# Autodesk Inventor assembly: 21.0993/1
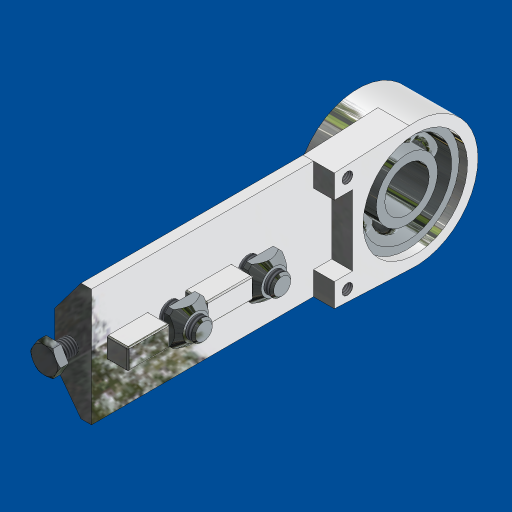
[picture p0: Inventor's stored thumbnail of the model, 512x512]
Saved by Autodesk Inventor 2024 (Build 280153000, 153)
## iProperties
Created: 2007-04
Part Number: 21.0993/1
Document SubType Name: Assembly
Designer: Andy Moles
Description: CONVEYOR BEARING 45 WITH BORE
Stock Number: 21.0993/1 CONVEYOR BEARING 45 WITH BORE
Author: Andy Moles
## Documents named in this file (6)
- L:\INVENTOR LIBRARIES\PARTS LIBRARY\BELT AND ROLLER CONVEYORS\21.0993_1 CONVEYOR BEARING 45 WITH BORE.iam
- L:\INVENTOR LIBRARIES\PARTS LIBRARY\BELT AND ROLLER CONVEYORS\SUBCOMPONENTS\21.0993_1 CONVEYOR BEARING 45 WITH BORE.ipt
- L:\INVENTOR LIBRARIES\PARTS LIBRARY\BELT AND ROLLER CONVEYORS\SUBCOMPONENTS\21.0993 CONVEYOR BEARING 45 M6X25.ipt
- L:\INVENTOR LIBRARIES\PARTS LIBRARY\FASTENING ELEMENTS\SCREWS CAP\21.1200 M8X16.ipt
- L:\INVENTOR LIBRARIES\PARTS LIBRARY\FASTENING ELEMENTS\NUTS\21.1351 M8 SQUARE NUT.ipt
- L:\INVENTOR LIBRARIES\PARTS LIBRARY\BELT AND ROLLER CONVEYORS\SUBCOMPONENTS\21.0993 15mm GRAY END CAP SHORT.ipt
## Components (8 placed, 5 different names)
1. 21.0993_1 CONVEYOR BEARING 45 WITH BORE:1 — Flush:1, Mate:1, Flush:2, Insert:1, Insert:2, Insert:3, Insert:4, Insert:5, Insert:6, Insert:7
2. 21.0993 CONVEYOR BEARING 45 M6X25:1 — Insert:1
3. 21.1200 M8 x 16:1 — Insert:2
4. 21.1200 M8 x 16:2 — Insert:3
5. 21.1351 M8 SQUARE NUT:1 — Insert:4
6. 21.1351 M8 SQUARE NUT:2 — Insert:5
7. 21.0993 15mm GRAY END CAP SHORT:1 — Insert:6
8. 21.0993 15mm GRAY END CAP SHORT:2 — Insert:7
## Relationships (10: Insert 7, Flush 2, Mate 1)
- Flush:1: 21.0993_1 CONVEYOR BEARING 45 WITH BORE:1
- Mate:1: 21.0993_1 CONVEYOR BEARING 45 WITH BORE:1
- Flush:2: 21.0993_1 CONVEYOR BEARING 45 WITH BORE:1
- Insert:1: 21.0993_1 CONVEYOR BEARING 45 WITH BORE:1 ↔ 21.0993 CONVEYOR BEARING 45 M6X25:1
- Insert:2: 21.0993_1 CONVEYOR BEARING 45 WITH BORE:1 ↔ 21.1200 M8 x 16:1
- Insert:3: 21.0993_1 CONVEYOR BEARING 45 WITH BORE:1 ↔ 21.1200 M8 x 16:2
- Insert:4: 21.0993_1 CONVEYOR BEARING 45 WITH BORE:1 ↔ 21.1351 M8 SQUARE NUT:1
- Insert:5: 21.0993_1 CONVEYOR BEARING 45 WITH BORE:1 ↔ 21.1351 M8 SQUARE NUT:2
- Insert:6: 21.0993_1 CONVEYOR BEARING 45 WITH BORE:1 ↔ 21.0993 15mm GRAY END CAP SHORT:1
- Insert:7: 21.0993_1 CONVEYOR BEARING 45 WITH BORE:1 ↔ 21.0993 15mm GRAY END CAP SHORT:2
